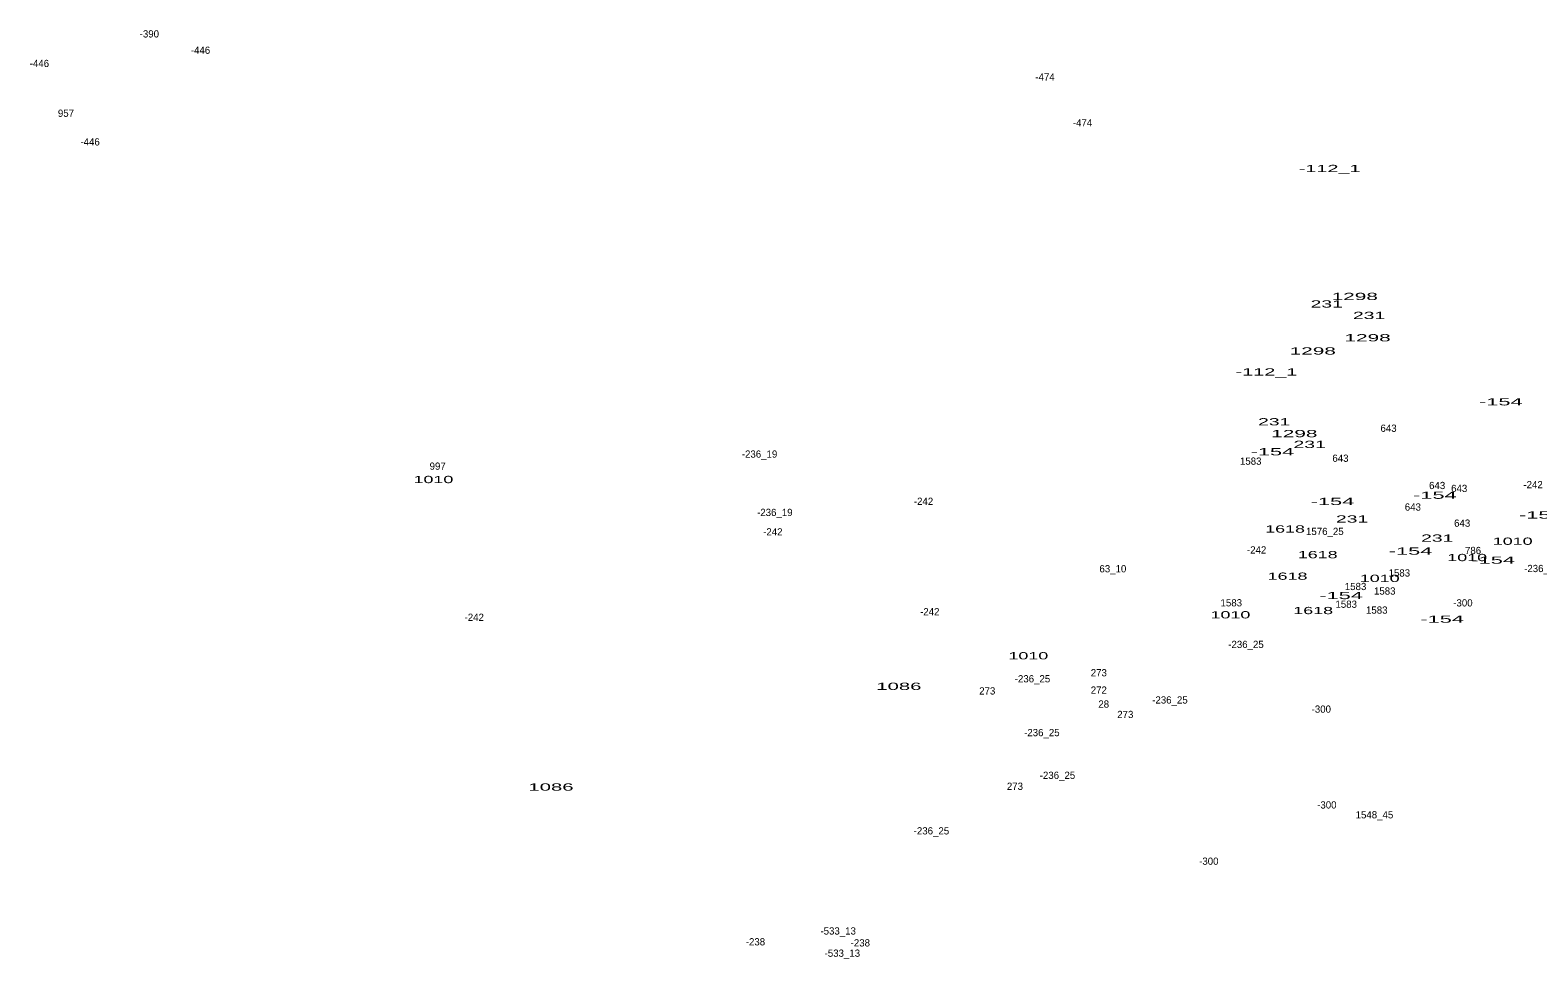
# Model space of a CAD drawing. Extents: x -660434 to -656144, y -997850 to -994016.
# Drawn here: x -660308 to -659474, y -996075 to -995561 of the extents above; entities that cross this region are included whole.
import ezdxf
from ezdxf.enums import TextEntityAlignment as Align

# ---------------------------------------------------------------- set-up
doc = ezdxf.new("R2010")
doc.units = 0
doc.header["$LTSCALE"] = 1.6
doc.layers.add('24', color=7, linetype='Continuous')

msp = doc.modelspace()

# ---------------------------------------------------------------- texts
at = {"layer": '24'}
for s, p in [('-390', (-660241.894, -995565.08)), ('-446', (-660213.609, -995574.12)), ('-446', (-660302.699, -995581.42)), ('-474', (-659746.579, -995588.93)), ('957', (-660288.008, -995608.97)), ('-474', (-659725.849, -995614.28)), ('-446', (-660274.669, -995624.83)), ('643', (-659556.617, -995783.24)), ('-236_19', (-659904.456, -995797.55)), ('1583', (-659632.83, -995801.46)), ('643', (-659583.207, -995799.84)), ('997', (-660082.453, -995804.22)), ('643', (-659529.737, -995814.92)), ('643', (-659517.537, -995816.55)), ('-242', (-659476.689, -995814.46)), ('-242', (-659813.779, -995823.68)), ('643', (-659543.177, -995826.83)), ('-236_19', (-659895.996, -995829.83)), ('-242', (-659897.109, -995840.58)), ('1576_25', (-659591.839, -995840.34)), ('643', (-659515.907, -995835.76)), ('-242', (-659629.559, -995850.57)), ('786', (-659509.878, -995850.89)), ('63_10', (-659709.058, -995861)), ('1583', (-659550.65, -995863.31)), ('-236_1', (-659473.302, -995860.85)), ('1583', (-659574.85, -995870.8)), ('1583', (-659558.72, -995873.3)), ('-242', (-659810.319, -995884.76)), ('1583', (-659643.58, -995879.83)), ('1583', (-659580.03, -995880.6)), ('1583', (-659563.13, -995883.86)), ('-300', (-659515.473, -995879.87)), ('-242', (-660062.229, -995887.83)), ('-236_25', (-659635.447, -995902.84)), ('273', (-659716.833, -995918.53)), ('-236_25', (-659753.527, -995921.86)), ('273', (-659778.533, -995928.57)), ('272', (-659716.833, -995928.13)), ('-236_25', (-659677.497, -995933.57)), ('28', (-659714.127, -995935.85)), ('273', (-659702.193, -995941.61)), ('-300', (-659593.803, -995938.64)), ('-236_25', (-659748.337, -995951.63)), ('-236_25', (-659739.707, -995975.25)), ('273', (-659763.223, -995981.32)), ('-300', (-659590.733, -995991.65)), ('1548_45', (-659564.407, -995997.11)), ('-236_25', (-659809.407, -996005.99)), ('-300', (-659656.013, -996022.77)), ('-238', (-659906.715, -996067.38)), ('-533_13', (-659860.975, -996061.37)), ('-238', (-659848.735, -996067.96)), ('-533_13', (-659858.675, -996073.66))]:
    msp.add_text(s, height=4, dxfattribs=at).set_placement(p, align=Align.CENTER)
for s, width, p in [('-112_1', 2.05, (-659589.174, -995639.54)), ('1298', 2.15, (-659575.303, -995710.34)), ('231', 2, (-659590.817, -995714.49)), ('231', 2, (-659567.367, -995720.84)), ('1298', 2.15, (-659568.203, -995733.2)), ('1298', 2.15, (-659598.533, -995740.5)), ('-112_1', 2.05, (-659624.124, -995752.09)), ('-154', 2.25, (-659494.506, -995768.63)), ('231', 2, (-659619.847, -995779.68)), ('1298', 2.15, (-659608.713, -995786.21)), ('231', 2, (-659600.237, -995792.18)), ('-154', 2.25, (-659620.846, -995796.28)), ('1010', 1.85, (-660084.806, -995811.62)), ('-154', 2.25, (-659587.626, -995823.75)), ('-154', 2.25, (-659530.986, -995820.3)), ('231', 2, (-659576.787, -995833.45)), ('-154', 2.25, (-659472.426, -995831.25)), ('1618', 1.85, (-659613.829, -995838.98)), ('-154', 2.25, (-659544.426, -995851.22)), ('231', 2, (-659529.687, -995844.03)), ('1010', 1.85, (-659487.966, -995845.75)), ('1618', 1.85, (-659595.779, -995853.19)), ('1010', 1.85, (-659513.116, -995854.78)), ('-154', 2.25, (-659498.736, -995856.22)), ('1618', 1.85, (-659612.479, -995865.1)), ('1010', 1.85, (-659561.506, -995866.3)), ('-154', 2.25, (-659582.836, -995875.8)), ('1618', 1.85, (-659598.289, -995884.11)), ('1010', 1.85, (-659644.056, -995886.47)), ('-154', 2.25, (-659526.956, -995888.86)), ('1010', 1.85, (-659755.806, -995909.14)), ('1086', 2.1, (-659827.409, -995926.04)), ('1086', 2.1, (-660019.799, -995981.75))]:
    msp.add_text(s, height=4, dxfattribs=dict(at, width=width)).set_placement(p, align=Align.CENTER)

doc.saveas('drawing.dxf')
